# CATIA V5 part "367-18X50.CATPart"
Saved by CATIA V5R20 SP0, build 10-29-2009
Part number: 367-18X50
Definition: NONE
Nomenclature: 367-18X50
Source: Unknown
Description: 367-18X50
Bounding box of the stored display mesh (mm): x 0 to 50, y -14 to 14, z -14 to 14
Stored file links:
  C:\Users\Utente\Desktop\IO LAVORO\3D X SITO CF\X SITO\PLASTICA\3D files 367\367-18X50.CATPart
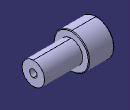
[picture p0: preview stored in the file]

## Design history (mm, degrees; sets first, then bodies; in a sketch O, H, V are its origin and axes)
Body1 "367-18X50" (main body)
  Solid1: solid without history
